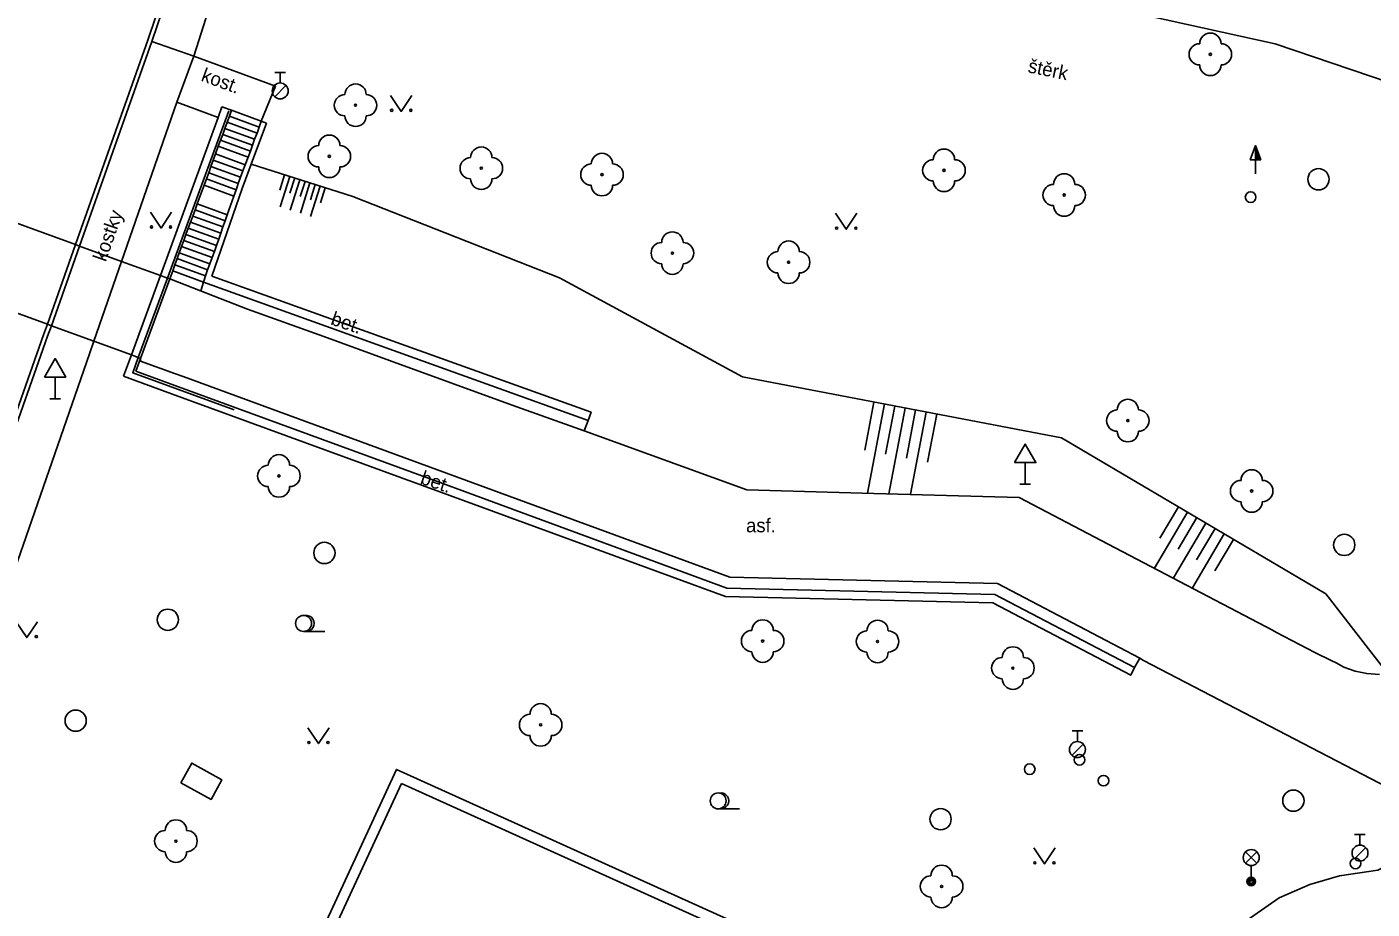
# Model space of a CAD drawing. Extents: x -598932 to -598196, y -1162207 to -1161504.
# Drawn here: x -598567.3 to -598504.1, y -1162110.3 to -1162068.8 of the extents above; entities that cross this region are included whole.
import ezdxf

# ---------------------------------------------------------------- set-up
doc = ezdxf.new("R2010")
doc.units = 0
for name, color, linetype in [('Level 22', 7, 'Continuous'), ('Level 25', 7, 'Continuous'), ('Level 27', 7, 'Continuous'), ('Level 28', 7, 'Continuous'), ('Level 33', 7, 'Continuous'), ('Level 34', 7, 'Continuous'), ('Level 36', 7, 'Continuous'), ('specificka linie pasportu komunikaci', 7, 'Continuous'), ('TM - budovy zdene_ betonove - VP', 7, 'Continuous'), ('TM - chodniky - NP', 7, 'Continuous'), ('TM - chodniky - VP', 7, 'Continuous'), ('TM - horni hrana svahu', 7, 'Continuous'), ('TM - komunikace - VP', 7, 'Continuous'), ('TM - letecke snimky - pomocna linie', 7, 'Continuous'), ('TM - popis povrchu', 7, 'Continuous'), ('TM - rozhrani ploch obecne - VP', 7, 'Continuous'), ('TM - srafovani', 7, 'Continuous'), ('TM - zabradli - VP', 7, 'Continuous')]:
    doc.layers.add(name, color=color, linetype=linetype)

msp = doc.modelspace()

# ---------------------------------------------------------------- linework, layer by layer
at = {"layer": 'Level 22'}
for centre in [(-598511.71, -1162070.1), (-598551.88, -1162072.49), (-598553.11, -1162074.89), (-598545.97, -1162075.45), (-598540.3, -1162075.75), (-598524.23, -1162075.55), (-598518.58, -1162076.71), (-598536.99, -1162079.44), (-598531.53, -1162079.87), (-598515.59, -1162087.31), (-598555.48, -1162089.91), (-598509.77, -1162090.62), (-598532.75, -1162097.67), (-598527.35, -1162097.69), (-598520.99, -1162098.94), (-598543.18, -1162101.61), (-598560.32, -1162107.07), (-598524.34, -1162109.2)]:
    msp.add_circle(centre, 0.05, dxfattribs=at)
for centre, start, end in [((-598511.71, -1162069.6), 0, 180), ((-598512.21, -1162070.1), 90, 270), ((-598511.21, -1162070.1), 270, 90), ((-598511.71, -1162070.6), 180, 0), ((-598552.38, -1162072.49), 90, 270), ((-598551.88, -1162071.99), 0, 180), ((-598551.38, -1162072.49), 270, 90), ((-598551.88, -1162072.99), 180, 0), ((-598553.11, -1162074.39), 0, 180), ((-598553.61, -1162074.89), 90, 270), ((-598552.61, -1162074.89), 270, 90), ((-598545.97, -1162074.95), 0, 180), ((-598524.23, -1162075.05), 0, 180), ((-598546.47, -1162075.45), 90, 270), ((-598545.47, -1162075.45), 270, 90), ((-598540.8, -1162075.75), 90, 270), ((-598540.3, -1162075.25), 0, 180), ((-598539.8, -1162075.75), 270, 90), ((-598524.73, -1162075.55), 90, 270), ((-598523.73, -1162075.55), 270, 90), ((-598553.11, -1162075.39), 180, 0), ((-598518.58, -1162076.21), 0, 180), ((-598545.97, -1162075.95), 180, 0), ((-598540.3, -1162076.25), 180, 0), ((-598524.23, -1162076.05), 180, 0), ((-598519.08, -1162076.71), 90, 270), ((-598518.08, -1162076.71), 270, 90), ((-598518.58, -1162077.21), 180, 0), ((-598537.49, -1162079.44), 90, 270), ((-598536.99, -1162078.94), 0, 180), ((-598536.49, -1162079.44), 270, 90), ((-598531.53, -1162079.37), 0, 180), ((-598532.03, -1162079.87), 90, 270), ((-598531.03, -1162079.87), 270, 90), ((-598536.99, -1162079.94), 180, 0), ((-598531.53, -1162080.37), 180, 0), ((-598515.59, -1162086.81), 0, 180), ((-598516.09, -1162087.31), 90, 270), ((-598515.09, -1162087.31), 270, 90), ((-598515.59, -1162087.81), 180, 0), ((-598555.48, -1162089.41), 0, 180), ((-598555.98, -1162089.91), 90, 270), ((-598554.98, -1162089.91), 270, 90), ((-598509.77, -1162090.12), 0, 180), ((-598555.48, -1162090.41), 180, 0), ((-598510.27, -1162090.62), 90, 270), ((-598509.27, -1162090.62), 270, 90), ((-598509.77, -1162091.12), 180, 0), ((-598532.75, -1162097.17), 0, 180), ((-598527.35, -1162097.19), 0, 180), ((-598533.25, -1162097.67), 90, 270), ((-598532.25, -1162097.67), 270, 90), ((-598527.85, -1162097.69), 90, 270), ((-598526.85, -1162097.69), 270, 90), ((-598520.99, -1162098.44), 0, 180), ((-598532.75, -1162098.17), 180, 0), ((-598527.35, -1162098.19), 180, 0), ((-598521.49, -1162098.94), 90, 270), ((-598520.49, -1162098.94), 270, 90), ((-598520.99, -1162099.44), 180, 0), ((-598543.68, -1162101.61), 90, 270), ((-598543.18, -1162101.11), 0, 180), ((-598542.68, -1162101.61), 270, 90), ((-598543.18, -1162102.11), 180, 0), ((-598560.32, -1162106.57), 0, 180), ((-598560.82, -1162107.07), 90, 270), ((-598559.82, -1162107.07), 270, 90), ((-598560.32, -1162107.57), 180, 0), ((-598524.84, -1162109.2), 90, 270), ((-598524.34, -1162108.7), 0, 180), ((-598523.84, -1162109.2), 270, 90), ((-598524.34, -1162109.7), 180, 0)]:
    msp.add_arc(centre, 0.5, start, end, dxfattribs=at)
at = {"layer": 'Level 25'}
for p, q in [((-598509.842, -1162075.058), (-598509.59, -1162074.384)), ((-598509.59, -1162075.058), (-598509.842, -1162075.058)), ((-598509.59, -1162075.71), (-598509.59, -1162075.06))]:
    msp.add_line(p, q, dxfattribs=at)
for points in [[(-598509.34, -1162075.06), (-598509.59, -1162075.06), (-598509.59, -1162074.384), (-598509.59, -1162074.384)], [(-598509.397, -1162075.02), (-598509.55, -1162075.02), (-598509.55, -1162074.607)], [(-598509.455, -1162074.98), (-598509.51, -1162074.98), (-598509.51, -1162074.831)]]:
    msp.add_lwpolyline(points, close=True, dxfattribs=at)
at = {"layer": 'Level 27'}
for centre in [(-598506.63, -1162075.97), (-598505.42, -1162093.15), (-598553.34, -1162093.53), (-598560.7, -1162096.67), (-598565.03, -1162101.41), (-598507.81, -1162105.17), (-598524.39, -1162106.04)]:
    msp.add_circle(centre, 0.5, dxfattribs=at)
at = {"layer": 'Level 28'}
for p, q in [((-598555.67, -1162070.945), (-598555.17, -1162070.945)), ((-598555.42, -1162071.445), (-598555.42, -1162070.945)), ((-598555.678, -1162072.092), (-598555.148, -1162071.562)), ((-598518.21, -1162101.895), (-598517.71, -1162101.895)), ((-598517.96, -1162102.395), (-598517.96, -1162101.895)), ((-598518.218, -1162103.042), (-598517.688, -1162102.512)), ((-598504.93, -1162106.755), (-598504.43, -1162106.755)), ((-598504.68, -1162107.255), (-598504.68, -1162106.755)), ((-598504.938, -1162107.902), (-598504.408, -1162107.372))]:
    msp.add_line(p, q, dxfattribs=at)
for centre, radius in [((-598555.42, -1162071.82), 0.375), ((-598509.82, -1162076.81), 0.25), ((-598517.96, -1162102.77), 0.375), ((-598517.86, -1162103.25), 0.25), ((-598520.2, -1162103.69), 0.25), ((-598516.73, -1162104.23), 0.25), ((-598504.68, -1162107.63), 0.375), ((-598504.89, -1162108.12), 0.25)]:
    msp.add_circle(centre, radius, dxfattribs=at)
at = {"layer": 'Level 33'}
for p, q in [((-598510.055, -1162108.11), (-598509.525, -1162107.58)), ((-598510.055, -1162107.58), (-598509.525, -1162108.11)), ((-598509.79, -1162108.22), (-598509.79, -1162108.97))]:
    msp.add_line(p, q, dxfattribs=at)
for centre, radius in [((-598509.79, -1162107.845), 0.375), ((-598509.79, -1162108.97), 0.2), ((-598509.79, -1162108.97), 0.145), ((-598509.79, -1162108.97), 0.0876)]:
    msp.add_circle(centre, radius, dxfattribs=at)
at = {"layer": 'Level 34'}
for p, q in [((-598566, -1162085.262), (-598566, -1162086.28)), ((-598566.25, -1162086.28), (-598565.75, -1162086.28)), ((-598520.41, -1162089.282), (-598520.41, -1162090.3)), ((-598520.66, -1162090.3), (-598520.16, -1162090.3))]:
    msp.add_line(p, q, dxfattribs=at)
for points in [[(-598566.5, -1162085.262), (-598565.5, -1162085.262), (-598566, -1162084.396)], [(-598520.91, -1162089.282), (-598519.91, -1162089.282), (-598520.41, -1162088.416)]]:
    msp.add_lwpolyline(points, close=True, dxfattribs=at)
at = {"layer": 'Level 36'}
for p, q in [((-598554.32, -1162097.215), (-598553.32, -1162097.215)), ((-598534.84, -1162105.555), (-598533.84, -1162105.555))]:
    msp.add_line(p, q, dxfattribs=at)
for points in [[(-598550.23, -1162072.03), (-598549.73, -1162072.78), (-598549.23, -1162072.03)], [(-598561.52, -1162077.51), (-598561.02, -1162078.26), (-598560.52, -1162077.51)], [(-598529.32, -1162077.57), (-598528.82, -1162078.32), (-598528.32, -1162077.57)], [(-598567.83, -1162096.76), (-598567.33, -1162097.51), (-598566.83, -1162096.76)], [(-598554.12, -1162101.74), (-598553.62, -1162102.49), (-598553.12, -1162101.74)], [(-598520.01, -1162107.39), (-598519.51, -1162108.14), (-598519.01, -1162107.39)]]:
    msp.add_lwpolyline(points, dxfattribs=at)
for centre, radius in [((-598550.18, -1162072.73), 0.05), ((-598549.281, -1162072.73), 0.05), ((-598561.47, -1162078.21), 0.05), ((-598560.571, -1162078.21), 0.05), ((-598529.27, -1162078.27), 0.05), ((-598528.371, -1162078.27), 0.05), ((-598554.32, -1162096.84), 0.375), ((-598566.881, -1162097.46), 0.05), ((-598554.07, -1162102.44), 0.05), ((-598553.171, -1162102.44), 0.05), ((-598534.84, -1162105.18), 0.375), ((-598519.96, -1162108.09), 0.05), ((-598519.061, -1162108.09), 0.05)]:
    msp.add_circle(centre, radius, dxfattribs=at)
for centre in [(-598554.195, -1162096.84), (-598534.715, -1162105.18)]:
    msp.add_arc(centre, 0.375, 260.40593, 99.59407, dxfattribs=at)
at = {"layer": 'specificka linie pasportu komunikaci'}
for points in [[(-598559.03, -1162080.8), (-598559.156, -1162081.213)], [(-598541.13, -1162087.793), (-598540.95, -1162087.3)]]:
    msp.add_lwpolyline(points, dxfattribs=at)
at = {"layer": 'TM - budovy zdene_ betonove - VP'}
for points in [[(-598565.92, -1162139.39), (-598549.72, -1162104.36)], [(-598549.72, -1162104.36), (-598524.14, -1162115.92)]]:
    msp.add_lwpolyline(points, dxfattribs=at)
at = {"layer": 'TM - chodniky - NP'}
for points in [[(-598578.9, -1162073.99), (-598565.04, -1162079.04)], [(-598580.21, -1162077.74), (-598566.36, -1162082.78)], [(-598565.04, -1162079.04), (-598564.85, -1162079.11)], [(-598564.85, -1162079.11), (-598562.87, -1162079.83)], [(-598562.87, -1162079.83), (-598561.05, -1162080.49)], [(-598561.05, -1162080.49), (-598560.72, -1162080.61)], [(-598560.72, -1162080.61), (-598560.61, -1162080.65)], [(-598566.36, -1162082.78), (-598566.17, -1162082.85)], [(-598566.17, -1162082.85), (-598564.17, -1162083.58)], [(-598564.17, -1162083.58), (-598562.41, -1162084.22)], [(-598562.41, -1162084.22), (-598561.98, -1162084.39)]]:
    msp.add_lwpolyline(points, dxfattribs=at)
at = {"layer": 'TM - chodniky - VP'}
for points in [[(-598555.64, -1162071.6), (-598556.31, -1162073.24)], [(-598560.28, -1162072.35), (-598562.87, -1162079.83)], [(-598560.28, -1162072.35), (-598558.34, -1162073.06)], [(-598562.87, -1162079.83), (-598564.17, -1162083.58)], [(-598564.17, -1162083.58), (-598564.38, -1162084.18)], [(-598585.89, -1162146.11), (-598585.7, -1162145.58), (-598585.61, -1162145.31), (-598581.26, -1162132.82), (-598576.27, -1162118.43), (-598574.63, -1162113.71), (-598570.89, -1162102.92), (-598564.38, -1162084.18)], [(-598561.98, -1162084.39), (-598561.98, -1162084.51), (-598560.344, -1162085.11), (-598559.986, -1162085.241), (-598534.29, -1162094.66), (-598521.71, -1162094.96), (-598515.03, -1162098.48)], [(-598515.03, -1162098.48), (-598514.85, -1162098.58), (-598503.8, -1162104.33), (-598503.437, -1162104.513), (-598503.115, -1162104.761), (-598502.843, -1162105.063), (-598502.632, -1162105.41), (-598502.488, -1162105.79), (-598502.418, -1162106.19), (-598502.422, -1162106.597), (-598502.5, -1162106.995), (-598502.651, -1162107.373), (-598502.869, -1162107.716), (-598503.146, -1162108.013), (-598503.474, -1162108.254), (-598503.84, -1162108.43)]]:
    msp.add_lwpolyline(points, dxfattribs=at)
at = {"layer": 'TM - horni hrana svahu'}
for points in [[(-598508.67, -1162069.6), (-598534.92, -1162063.81)], [(-598497.9, -1162073.25), (-598508.67, -1162069.6)], [(-598556.78, -1162075.26), (-598552.01, -1162076.78)], [(-598552.01, -1162076.78), (-598542.29, -1162080.6), (-598533.7, -1162085.26), (-598518.7, -1162088.12), (-598506.29, -1162095.45), (-598503.36, -1162099.22)]]:
    msp.add_lwpolyline(points, dxfattribs=at)
at = {"layer": 'TM - komunikace - VP'}
for points in [[(-598559.58, -1162063.97), (-598561.45, -1162069.5)], [(-598561.45, -1162069.5), (-598564.85, -1162079.11)], [(-598564.85, -1162079.11), (-598566.17, -1162082.85)], [(-598566.17, -1162082.85), (-598566.35, -1162083.35), (-598568.34, -1162089.02)], [(-598511.78, -1162112.35), (-598510.34, -1162111.04), (-598508.47, -1162109.74), (-598507.04, -1162109.11), (-598505.65, -1162108.7), (-598503.84, -1162108.43)]]:
    msp.add_lwpolyline(points, dxfattribs=at)
at = {"layer": 'TM - letecke snimky - pomocna linie'}
for points in [[(-598557.71, -1162064.61), (-598559.48, -1162070.19)], [(-598503.77, -1162099.24), (-598504.36, -1162099.2), (-598504.9, -1162099.09), (-598505.44, -1162098.89), (-598505.8, -1162098.7), (-598506.01, -1162098.6), (-598506.8, -1162098.2), (-598508.6, -1162097.26), (-598508.79, -1162097.16), (-598516.52, -1162093.11), (-598520.69, -1162090.92), (-598527.53, -1162090.73), (-598533.5, -1162090.57), (-598541.13, -1162087.79), (-598544.52, -1162086.58), (-598550.29, -1162084.48), (-598553.37, -1162083.36), (-598556.95, -1162082.07), (-598559.16, -1162081.21), (-598560.61, -1162080.65)]]:
    msp.add_lwpolyline(points, dxfattribs=at)
at = {"layer": 'TM - rozhrani ploch obecne - VP'}
for points in [[(-598558.65, -1162060.76), (-598559.1, -1162062.03), (-598559.77, -1162063.9), (-598561.64, -1162069.44), (-598565.04, -1162079.04)], [(-598561.45, -1162069.5), (-598559.48, -1162070.19)], [(-598559.48, -1162070.19), (-598560.28, -1162072.35)], [(-598559.48, -1162070.19), (-598555.64, -1162071.6)], [(-598558.16, -1162072.57), (-598558.34, -1162073.06)], [(-598558.16, -1162072.57), (-598557.71, -1162072.73)], [(-598557.71, -1162072.73), (-598557.81, -1162073.01)], [(-598557.71, -1162072.73), (-598556.31, -1162073.24)], [(-598558.34, -1162073.06), (-598561.05, -1162080.49)], [(-598557.91, -1162073.29), (-598558.02, -1162073.58)], [(-598557.81, -1162073.01), (-598557.91, -1162073.29)], [(-598557.91, -1162073.29), (-598556.51, -1162073.8)], [(-598557.81, -1162073.01), (-598556.41, -1162073.52)], [(-598556.07, -1162073.33), (-598556.78, -1162075.26)], [(-598556.31, -1162073.24), (-598556.41, -1162073.52)], [(-598556.31, -1162073.24), (-598556.07, -1162073.33)], [(-598558.12, -1162073.86), (-598558.22, -1162074.14)], [(-598558.02, -1162073.58), (-598558.12, -1162073.86)], [(-598558.12, -1162073.86), (-598556.72, -1162074.37)], [(-598558.02, -1162073.58), (-598556.62, -1162074.09)], [(-598556.51, -1162073.8), (-598556.62, -1162074.09)], [(-598556.41, -1162073.52), (-598556.51, -1162073.8)], [(-598558.33, -1162074.42), (-598558.46, -1162074.78)], [(-598558.22, -1162074.14), (-598558.33, -1162074.42)], [(-598558.33, -1162074.42), (-598556.93, -1162074.93)], [(-598558.22, -1162074.14), (-598556.82, -1162074.65)], [(-598556.72, -1162074.37), (-598556.82, -1162074.65)], [(-598556.62, -1162074.09), (-598556.72, -1162074.37)], [(-598558.57, -1162075.07), (-598558.68, -1162075.37)], [(-598558.46, -1162074.78), (-598558.57, -1162075.07)], [(-598558.57, -1162075.07), (-598557.17, -1162075.58)], [(-598558.46, -1162074.78), (-598557.06, -1162075.29)], [(-598556.78, -1162075.26), (-598557.2, -1162076.4)], [(-598556.93, -1162074.93), (-598557.06, -1162075.29)], [(-598556.82, -1162074.65), (-598556.93, -1162074.93)], [(-598558.78, -1162075.66), (-598558.89, -1162075.95)], [(-598558.68, -1162075.37), (-598558.78, -1162075.66)], [(-598558.78, -1162075.66), (-598557.39, -1162076.17)], [(-598558.68, -1162075.37), (-598557.28, -1162075.87)], [(-598557.28, -1162075.87), (-598557.39, -1162076.17)], [(-598557.17, -1162075.58), (-598557.28, -1162075.87)], [(-598557.06, -1162075.29), (-598557.17, -1162075.58)], [(-598559, -1162076.25), (-598559.32, -1162077.13)], [(-598558.89, -1162075.95), (-598559, -1162076.25)], [(-598559, -1162076.25), (-598557.6, -1162076.76)], [(-598558.89, -1162075.95), (-598557.49, -1162076.46)], [(-598557.2, -1162076.4), (-598558.63, -1162080.52)], [(-598557.6, -1162076.76), (-598557.49, -1162076.46)], [(-598557.49, -1162076.46), (-598557.44, -1162076.32)], [(-598557.39, -1162076.17), (-598557.44, -1162076.32)], [(-598559.32, -1162077.13), (-598559.42, -1162077.41)], [(-598559.32, -1162077.13), (-598557.91, -1162077.64)], [(-598557.91, -1162077.64), (-598557.6, -1162076.76)], [(-598559.53, -1162077.7), (-598559.63, -1162077.98)], [(-598559.42, -1162077.41), (-598559.53, -1162077.7)], [(-598559.53, -1162077.7), (-598558.11, -1162078.21)], [(-598559.42, -1162077.41), (-598558.01, -1162077.93)], [(-598558.01, -1162077.93), (-598557.91, -1162077.64)], [(-598559.74, -1162078.27), (-598559.85, -1162078.56)], [(-598559.63, -1162077.98), (-598559.74, -1162078.27)], [(-598559.74, -1162078.27), (-598558.31, -1162078.79)], [(-598559.63, -1162077.98), (-598558.21, -1162078.5)], [(-598558.21, -1162078.5), (-598558.11, -1162078.21)], [(-598558.11, -1162078.21), (-598558.01, -1162077.93)], [(-598565.04, -1162079.04), (-598566.36, -1162082.78)], [(-598559.95, -1162078.84), (-598560.06, -1162079.13)], [(-598559.85, -1162078.56), (-598559.95, -1162078.84)], [(-598559.95, -1162078.84), (-598558.51, -1162079.36)], [(-598559.85, -1162078.56), (-598558.41, -1162079.08)], [(-598558.41, -1162079.08), (-598558.31, -1162078.79)], [(-598558.31, -1162078.79), (-598558.21, -1162078.5)], [(-598560.16, -1162079.42), (-598560.26, -1162079.7)], [(-598560.06, -1162079.13), (-598560.16, -1162079.42)], [(-598560.16, -1162079.42), (-598558.72, -1162079.94)], [(-598560.06, -1162079.13), (-598558.62, -1162079.65)], [(-598558.72, -1162079.94), (-598558.62, -1162079.65)], [(-598558.62, -1162079.65), (-598558.51, -1162079.36)], [(-598558.51, -1162079.36), (-598558.41, -1162079.08)], [(-598560.47, -1162080.28), (-598560.61, -1162080.65)], [(-598560.37, -1162079.99), (-598560.47, -1162080.28)], [(-598560.47, -1162080.28), (-598559.03, -1162080.8)], [(-598560.26, -1162079.7), (-598560.37, -1162079.99)], [(-598560.37, -1162079.99), (-598558.93, -1162080.51)], [(-598560.26, -1162079.7), (-598558.83, -1162080.23)], [(-598558.93, -1162080.51), (-598558.83, -1162080.23)], [(-598558.83, -1162080.23), (-598558.72, -1162079.94)], [(-598561.05, -1162080.49), (-598562.41, -1162084.22)], [(-598560.61, -1162080.65), (-598561.98, -1162084.39)], [(-598559.03, -1162080.8), (-598558.93, -1162080.51)], [(-598559.03, -1162080.8), (-598540.95, -1162087.3)], [(-598558.63, -1162080.52), (-598540.81, -1162086.92), (-598540.95, -1162087.3)], [(-598566.36, -1162082.78), (-598566.54, -1162083.28), (-598568.53, -1162088.95)], [(-598562.41, -1162084.22), (-598562.78, -1162085.23)], [(-598561.98, -1162084.39), (-598562.2, -1162084.99)], [(-598562.78, -1162085.23), (-598560.52, -1162086.054), (-598547.92, -1162090.65), (-598534.5, -1162095.58), (-598521.94, -1162095.87), (-598515.45, -1162099.28), (-598515.27, -1162098.92)], [(-598562.2, -1162084.99), (-598560.375, -1162085.658), (-598547.78, -1162090.27), (-598534.43, -1162095.18), (-598521.84, -1162095.48), (-598515.27, -1162098.92)], [(-598515.27, -1162098.92), (-598515.03, -1162098.48)], [(-598553.57, -1162145.58), (-598566.58, -1162139.64), (-598549.96, -1162103.7), (-598523.48, -1162115.67), (-598530.38, -1162130.76)], [(-598560.09, -1162104.33), (-598559.58, -1162103.4), (-598558.17, -1162104.19), (-598558.67, -1162105.11), (-598560.09, -1162104.33)]]:
    msp.add_lwpolyline(points, dxfattribs=at)
at = {"layer": 'TM - srafovani'}
for points in [[(-598555.21, -1162075.76), (-598555.43, -1162076.48)], [(-598554.97, -1162075.84), (-598555.42, -1162077.27)], [(-598554.73, -1162075.91), (-598554.96, -1162076.63)], [(-598554.49, -1162075.99), (-598554.95, -1162077.42)], [(-598554.25, -1162076.07), (-598554.48, -1162076.78)], [(-598554.02, -1162076.14), (-598554.47, -1162077.57)], [(-598553.78, -1162076.22), (-598554, -1162076.93)], [(-598553.54, -1162076.29), (-598553.99, -1162077.72)], [(-598553.3, -1162076.37), (-598553.53, -1162077.08)], [(-598527.95, -1162088.7), (-598527.52, -1162086.44)], [(-598527.83, -1162090.72), (-598527.03, -1162086.53)], [(-598526.97, -1162088.88), (-598526.54, -1162086.63)], [(-598526.82, -1162090.75), (-598526.05, -1162086.72)], [(-598525.99, -1162089.07), (-598525.56, -1162086.81)], [(-598525.8, -1162090.77), (-598525.07, -1162086.91)], [(-598525.01, -1162089.26), (-598524.57, -1162087)], [(-598514.33, -1162094.24), (-598512.78, -1162091.62)], [(-598514.09, -1162092.84), (-598513.21, -1162091.36)], [(-598513.44, -1162094.7), (-598511.92, -1162092.13)], [(-598513.23, -1162093.35), (-598512.35, -1162091.87)], [(-598512.55, -1162095.17), (-598511.06, -1162092.63)], [(-598512.36, -1162093.86), (-598511.49, -1162092.38)], [(-598511.5, -1162094.37), (-598510.63, -1162092.89)]]:
    msp.add_lwpolyline(points, dxfattribs=at)
at = {"layer": 'TM - zabradli - VP'}
for points in [[(-598557.84, -1162072.76), (-598560.72, -1162080.61)], [(-598560.72, -1162080.61), (-598562.09, -1162084.34)], [(-598562.09, -1162084.34), (-598562.35, -1162085.06), (-598557.58, -1162086.8)]]:
    msp.add_lwpolyline(points, dxfattribs=at)

# ---------------------------------------------------------------- texts
at = {"layer": 'TM - popis povrchu'}
for s, rotation, p in [('kost.', 339.84, (-598559.18, -1162071.33)), ('štěrk', 348.42, (-598520.32, -1162070.94)), ('kostky', 70.64, (-598563.62, -1162079.88)), ('bet.', 341.22, (-598553.09, -1162082.78)), ('bet.', 341.22, (-598548.88, -1162090.26))]:
    msp.add_text(s, height=0.65, rotation=rotation, dxfattribs=at).set_placement(p)
msp.add_text('asf.', height=0.65, dxfattribs=at).set_placement((-598533.53, -1162092.56))

doc.saveas('drawing.dxf')
